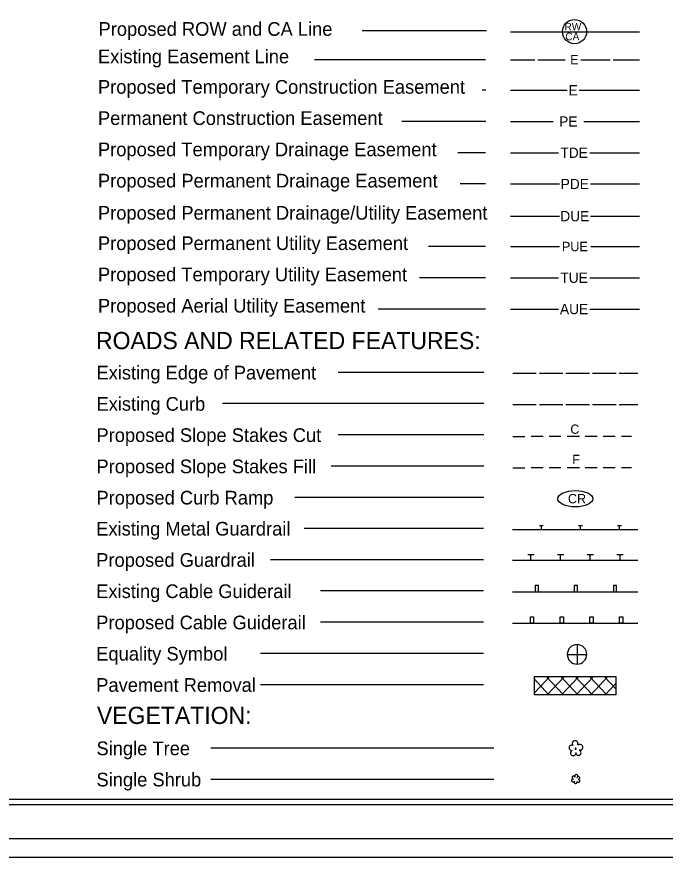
# Model space of a CAD drawing. Extents: x 811508 to 813252, y 647626 to 648754.
# Drawn here: x 811937 to 812366, y 647626 to 648182 of the extents above; entities that cross this region are included whole.
import ezdxf

# ---------------------------------------------------------------- set-up
doc = ezdxf.new("R2010")
doc.units = 0
for name, color, linetype in [('P_RDY_Easement_Permanent', 7, 'Continuous'), ('P_RDY_Easement_Permanent_Drainage_Utility', 7, 'Continuous'), ('P_RDY_WCC_CELL', 7, 'Continuous'), ('Sheet Cutting Line CELL', 7, 'Continuous'), ('Sheet Plot Border Inside CELL', 7, 'Continuous'), ('Sheet Plot Border Outside CELL', 7, 'Continuous'), ('Sheet_Plan', 7, 'Continuous'), ('Sheet_Symbology', 7, 'Continuous'), ('z - Construction', 7, 'Continuous')]:
    doc.layers.add(name, color=color, linetype=linetype)

msp = doc.modelspace()

# ---------------------------------------------------------------- linework, layer by layer
at = {"layer": 'P_RDY_Easement_Permanent'}
for p, q in [((812264.02, 648112.84), (812292.21, 648112.84)), ((812312.7, 648112.84), (812340.89, 648112.84)), ((812340.89, 648112.84), (812349.4, 648112.84))]:
    msp.add_line(p, q, dxfattribs=at)
at = {"layer": 'P_RDY_Easement_Permanent_Drainage_Utility'}
for p, q in [((812264.02, 648050.14), (812296.41, 648050.14)), ((812317.11, 648050.14), (812349.4, 648050.14))]:
    msp.add_line(p, q, dxfattribs=at)
at = {"layer": 'P_RDY_WCC_CELL'}
msp.add_ellipse((812306.97, 647863), major_axis=(11.61, 0), ratio=0.462467, dxfattribs=at)
at = {"layer": 'Sheet Cutting Line CELL'}
msp.add_line((811533.6, 647637.99), (813217.6, 647637.99), dxfattribs=at)
at = {"layer": 'Sheet Plot Border Inside CELL'}
msp.add_lwpolyline([(811546.6, 647660.44), (813213.1, 647660.44), (813213.1, 648715.54), (811546.6, 648715.54)], close=True, dxfattribs=at)
at = {"layer": 'Sheet Plot Border Outside CELL'}
msp.add_lwpolyline([(811533.6, 647637.99), (813217.6, 647637.99), (813217.6, 648737.99), (811533.6, 648737.99)], close=True, dxfattribs=at)
at = {"layer": 'Sheet_Plan'}
msp.add_line((811546.61, 647664.09), (813213.5, 647664.09), dxfattribs=at)
at = {"layer": 'Sheet_Symbology'}
for p, q in [((812248.08, 648172.94), (812165.95, 648172.94)), ((812264.03, 648172.14), (812349.41, 648172.14)), ((812247.43, 648153.67), (812134.36, 648153.67)), ((812264.02, 648153.67), (812280.07, 648153.67)), ((812282.14, 648153.67), (812300.26, 648153.67)), ((812310.61, 648153.67), (812330.01, 648153.67)), ((812332.08, 648153.67), (812349.4, 648153.67)), ((812247.83, 648133.54), (812245.22, 648133.54)), ((812264.02, 648133.54), (812266.72, 648133.54)), ((812266.72, 648133.54), (812301.65, 648133.54)), ((812309.42, 648133.54), (812344.35, 648133.54)), ((812344.35, 648133.54), (812349.4, 648133.54)), ((812247.83, 648112.84), (812192.14, 648112.84)), ((812247.43, 648092.14), (812229.32, 648092.14)), ((812264.02, 648092.14), (812267.49, 648092.14)), ((812267.49, 648092.14), (812295.95, 648092.14)), ((812316.65, 648092.14), (812345.11, 648092.14)), ((812345.11, 648092.14), (812349.4, 648092.14)), ((812247.43, 648071.44), (812230.86, 648071.44)), ((812264.02, 648071.44), (812267.95, 648071.44)), ((812267.95, 648071.44), (812296.41, 648071.44)), ((812317.11, 648071.44), (812345.57, 648071.44)), ((812345.57, 648071.44), (812349.4, 648071.44)), ((812247.43, 648030.03), (812209.74, 648030.03)), ((812264.02, 648030.03), (812267.99, 648030.03)), ((812267.99, 648030.03), (812296.45, 648030.03)), ((812317.15, 648030.03), (812345.61, 648030.03)), ((812345.61, 648030.03), (812349.4, 648030.03)), ((812247.43, 648009.33), (812203.82, 648009.33)), ((812264.02, 648009.33), (812267.49, 648009.33)), ((812267.49, 648009.33), (812295.95, 648009.33)), ((812316.65, 648009.33), (812345.11, 648009.33)), ((812345.11, 648009.33), (812349.4, 648009.33)), ((812247.43, 647988.63), (812176.58, 647988.63)), ((812264.02, 647988.63), (812267.49, 647988.63)), ((812267.49, 647988.63), (812295.95, 647988.63)), ((812316.65, 647988.63), (812345.11, 647988.63)), ((812345.11, 647988.63), (812349.4, 647988.63)), ((812246.43, 647946.69), (812149.93, 647946.69)), ((812265.61, 647946.1), (812281.14, 647946.1)), ((812283.21, 647946.1), (812298.73, 647946.1)), ((812300.8, 647946.1), (812316.32, 647946.1)), ((812318.39, 647946.1), (812333.92, 647946.1)), ((812335.99, 647946.1), (812348.41, 647946.1)), ((812246.43, 647925.99), (812073.44, 647925.99)), ((812265.61, 647925.4), (812281.14, 647925.4)), ((812283.21, 647925.4), (812298.73, 647925.4)), ((812300.8, 647925.4), (812316.32, 647925.4)), ((812318.39, 647925.4), (812333.92, 647925.4)), ((812335.99, 647925.4), (812348.41, 647925.4)), ((812246.43, 647905.29), (812149.99, 647905.29)), ((812265.61, 647904.21), (812273.48, 647904.21)), ((812285.59, 647904.21), (812277.77, 647904.21)), ((812297.49, 647904.21), (812289.62, 647904.21)), ((812309.65, 647904.21), (812301.58, 647904.21)), ((812321.5, 647904.21), (812313.48, 647904.21)), ((812333.45, 647904.21), (812325.33, 647904.21)), ((812344.11, 647904.21), (812337.49, 647904.21)), ((812246.43, 647884.59), (812145.28, 647884.59)), ((812265.61, 647883.51), (812273.48, 647883.51)), ((812285.59, 647883.51), (812277.77, 647883.51)), ((812297.49, 647883.51), (812289.62, 647883.51)), ((812309.65, 647883.51), (812301.58, 647883.51)), ((812321.5, 647883.51), (812313.48, 647883.51)), ((812333.45, 647883.51), (812325.33, 647883.51)), ((812344.11, 647883.51), (812337.49, 647883.51)), ((812246.43, 647863.89), (812121.28, 647863.89)), ((812283.19, 647845.31), (812285.77, 647845.31)), ((812284.48, 647842.72), (812284.48, 647845.31)), ((812309.06, 647845.31), (812311.65, 647845.31)), ((812310.35, 647842.72), (812310.35, 647845.31)), ((812334.93, 647845.31), (812337.52, 647845.31)), ((812336.23, 647842.72), (812336.23, 647845.31)), ((812246.27, 647843.32), (812127.42, 647843.32)), ((812265.45, 647842.72), (812348.25, 647842.72)), ((812246.27, 647822.62), (812105.27, 647822.62)), ((812348.25, 647822.02), (812265.45, 647822.02)), ((812275.51, 647826.11), (812279.65, 647826.11)), ((812277.58, 647822.02), (812277.58, 647826.11)), ((812295.18, 647826.11), (812299.32, 647826.11)), ((812297.25, 647822.02), (812297.25, 647826.11)), ((812314.84, 647826.11), (812318.98, 647826.11)), ((812316.91, 647822.02), (812316.91, 647826.11)), ((812334.51, 647826.11), (812338.65, 647826.11)), ((812336.58, 647822.02), (812336.58, 647826.11)), ((812246.27, 647801.92), (812138.32, 647801.92)), ((812265.45, 647801.32), (812348.25, 647801.32)), ((812246.27, 647781.22), (812138.32, 647781.22)), ((812265.45, 647780.63), (812348.25, 647780.63)), ((812308.12, 647766.38), (812308.12, 647759.91)), ((812246.27, 647760.52), (812098.66, 647760.52)), ((812301.65, 647759.91), (812308.12, 647759.91)), ((812308.12, 647759.91), (812308.12, 647753.44)), ((812308.12, 647759.91), (812314.58, 647759.91)), ((812279.89, 647745.29), (812333.81, 647745.29)), ((812279.89, 647733.18), (812279.89, 647745.29)), ((812279.89, 647744.67), (812280.46, 647745.29)), ((812279.89, 647734.37), (812290.08, 647745.29)), ((812299.09, 647733.18), (812287.7, 647745.29)), ((812288.32, 647733.18), (812299.71, 647745.29)), ((812308.66, 647733.18), (812297.33, 647745.29)), ((812297.89, 647733.18), (812309.33, 647745.29)), ((812318.28, 647733.18), (812306.9, 647745.29)), ((812307.52, 647733.18), (812318.9, 647745.29)), ((812327.91, 647733.18), (812316.47, 647745.29)), ((812317.15, 647733.18), (812328.48, 647745.29)), ((812333.81, 647737.07), (812326.1, 647745.29)), ((812333.81, 647745.29), (812333.81, 647733.18)), ((812246.27, 647739.82), (812098.66, 647739.82)), ((812289.46, 647733.18), (812279.89, 647743.43)), ((812326.72, 647733.18), (812333.81, 647740.74)), ((812333.81, 647733.18), (812279.89, 647733.18)), ((812253.08, 647697.86), (812065.62, 647697.86)), ((812253.08, 647677.16), (812065.62, 647677.16))]:
    msp.add_line(p, q, dxfattribs=at)
for points in [[(812280.43, 647801.32), (812282.5, 647801.32), (812282.5, 647805.46), (812280.43, 647805.46)], [(812306.3, 647801.32), (812308.37, 647801.32), (812308.37, 647805.46), (812306.3, 647805.46)], [(812332.18, 647801.32), (812334.25, 647801.32), (812334.25, 647805.46), (812332.18, 647805.46)], [(812277.31, 647784.76), (812279.38, 647784.76), (812279.38, 647780.63), (812277.31, 647780.63)], [(812296.98, 647784.76), (812299.05, 647784.76), (812299.05, 647780.63), (812296.98, 647780.63)], [(812316.64, 647784.76), (812318.71, 647784.76), (812318.71, 647780.63), (812316.64, 647780.63)], [(812336.31, 647784.76), (812338.38, 647784.76), (812338.38, 647780.63), (812336.31, 647780.63)]]:
    msp.add_lwpolyline(points, close=True, dxfattribs=at)
for points in [[(812308.49, 647700.02), (812308.65, 647700.39), (812308.73, 647700.75), (812308.69, 647701.16), (812308.61, 647701.53), (812308.41, 647701.89), (812308.2, 647702.18), (812307.88, 647702.47), (812307.55, 647702.63), (812307.14, 647702.75), (812306.78, 647702.75), (812306.37, 647702.71), (812306, 647702.59), (812305.68, 647702.38), (812305.39, 647702.1), (812305.19, 647701.77), (812305.02, 647701.41), (812304.98, 647701.04), (812304.98, 647700.63), (812305.06, 647700.26), (812305.23, 647699.9), (812305.47, 647699.57), (812305.15, 647699.73), (812304.78, 647699.82), (812304.41, 647699.78), (812304.05, 647699.69), (812303.72, 647699.53), (812303.39, 647699.29), (812303.19, 647699), (812302.99, 647698.67), (812302.91, 647698.35), (812302.86, 647697.94), (812302.91, 647697.57), (812303.07, 647697.25), (812303.27, 647696.92), (812303.52, 647696.68), (812303.84, 647696.47), (812304.17, 647696.31), (812304.54, 647696.27), (812304.9, 647696.27), (812304.58, 647696.11), (812304.29, 647695.86), (812304.09, 647695.58), (812303.92, 647695.21), (812303.84, 647694.85), (812303.8, 647694.48), (812303.88, 647694.11), (812304.05, 647693.79), (812304.25, 647693.46), (812304.49, 647693.21), (812304.82, 647693.01), (812305.19, 647692.89), (812305.55, 647692.85), (812305.92, 647692.89), (812306.29, 647692.97), (812306.61, 647693.17), (812306.9, 647693.42), (812307.1, 647693.7), (812307.27, 647694.03), (812307.35, 647694.4)], [(812307.22, 647694.85), (812307.27, 647694.44), (812307.39, 647694.07), (812307.59, 647693.75), (812307.88, 647693.46), (812308.2, 647693.25), (812308.57, 647693.13), (812308.98, 647693.09), (812309.34, 647693.13), (812309.71, 647693.25), (812310.04, 647693.46), (812310.32, 647693.7), (812310.57, 647694.03), (812310.69, 647694.4), (812310.77, 647694.76), (812310.73, 647695.17), (812310.65, 647695.54), (812310.44, 647695.9), (812310.2, 647696.19), (812309.87, 647696.39), (812309.51, 647696.56), (812309.91, 647696.52), (812310.32, 647696.52), (812310.69, 647696.64), (812311.05, 647696.8), (812311.38, 647697.05), (812311.63, 647697.37), (812311.83, 647697.74), (812311.91, 647698.1), (812311.95, 647698.51), (812311.87, 647698.92), (812311.75, 647699.29), (812311.5, 647699.61), (812311.22, 647699.9), (812310.89, 647700.1), (812310.48, 647700.26), (812310.12, 647700.3), (812309.71, 647700.3), (812309.3, 647700.18), (812308.98, 647699.98), (812308.65, 647699.73)], [(812307.35, 647697.74), (812307.18, 647697.74), (812307.02, 647697.7), (812306.94, 647697.57), (812306.9, 647697.41), (812306.94, 647697.25), (812307.06, 647697.13), (812307.22, 647697.13), (812307.39, 647697.17), (812307.51, 647697.29), (812307.55, 647697.45), (812307.47, 647697.62), (812307.35, 647697.74)], [(812306.74, 647678.67), (812306.61, 647678.91), (812306.37, 647679.12), (812306.12, 647679.28), (812305.84, 647679.32), (812305.55, 647679.28), (812305.27, 647679.2), (812305.02, 647679), (812304.86, 647678.75), (812304.78, 647678.46), (812304.78, 647678.18), (812304.86, 647677.89), (812305.02, 647677.65), (812305.27, 647677.45), (812305.55, 647677.32), (812305.84, 647677.32), (812305.55, 647677.36), (812305.27, 647677.36), (812305.02, 647677.28), (812304.78, 647677.12), (812304.62, 647676.92), (812304.54, 647676.67), (812304.49, 647676.39), (812304.54, 647676.1), (812304.66, 647675.86), (812304.86, 647675.65), (812305.1, 647675.53), (812305.35, 647675.45), (812305.64, 647675.49), (812305.88, 647675.57), (812306.12, 647675.73), (812306.29, 647675.94), (812306.16, 647675.65), (812306.12, 647675.37), (812306.21, 647675.08), (812306.33, 647674.84), (812306.53, 647674.59), (812306.78, 647674.47), (812307.06, 647674.39), (812307.35, 647674.43), (812307.63, 647674.51), (812307.88, 647674.67), (812308.04, 647674.92), (812308.16, 647675.2), (812308.16, 647675.49), (812308.12, 647675.77), (812308.24, 647675.57), (812308.49, 647675.37), (812308.73, 647675.29), (812309.02, 647675.25), (812309.3, 647675.29), (812309.55, 647675.41), (812309.75, 647675.61), (812309.87, 647675.86), (812309.91, 647676.14), (812309.91, 647676.43), (812309.79, 647676.67), (812309.63, 647676.88), (812309.42, 647677.04), (812309.14, 647677.16), (812308.85, 647677.16), (812309.14, 647677.16), (812309.42, 647677.24), (812309.63, 647677.4), (812309.83, 647677.65), (812309.91, 647677.89), (812309.91, 647678.18), (812309.87, 647678.46), (812309.71, 647678.71), (812309.51, 647678.87), (812309.22, 647679), (812308.94, 647679.04), (812308.69, 647678.95), (812308.41, 647678.83), (812308.24, 647678.63), (812308.12, 647678.38)], [(812308, 647678.38), (812308.24, 647678.5), (812308.45, 647678.75), (812308.57, 647679), (812308.61, 647679.28), (812308.61, 647679.56), (812308.49, 647679.85), (812308.32, 647680.05), (812308.12, 647680.26), (812307.84, 647680.34), (812307.55, 647680.38), (812307.27, 647680.34), (812307.02, 647680.22), (812306.78, 647680.01), (812306.65, 647679.77), (812306.57, 647679.48), (812306.57, 647679.2), (812306.61, 647678.91), (812306.78, 647678.67)]]:
    msp.add_lwpolyline(points, dxfattribs=at)
msp.add_circle((812306.45, 648172.3), 7.99, dxfattribs=at)
for start, end in [(89.9944, 179.9989), (359.9944, 89.9989), (179.9944, 269.9989), (269.9944, 359.9989)]:
    msp.add_arc((812308.12, 647759.91), 6.47, start, end, dxfattribs=at)
at = {"layer": 'z - Construction'}
msp.add_line((811508.14, 647625.63), (813251.99, 647625.63), dxfattribs=at)

# ---------------------------------------------------------------- texts
at = {"layer": 'P_RDY_Easement_Permanent_Drainage_Utility'}
msp.add_text('DUE', height=6.779, dxfattribs=at).set_placement((812297.03, 648046.73))
at = {"layer": 'P_RDY_WCC_CELL'}
msp.add_text('CR', height=6.21, dxfattribs=at).set_placement((812302.09, 647859.94))
at = {"layer": 'Sheet_Symbology'}
for s, height, p in [('Proposed ROW and CA Line', 9.056, (811991.39, 648169.55)), ('RW', 5.008, (812299.78, 648173.09)), ('CA', 5.008, (812300.35, 648166.58)), ('Existing Easement Line', 9.056, (811991.01, 648151.33)), ('E', 6.21, (812303.57, 648150.57)), ('Proposed Temporary Construction Easement', 9.056, (811991.01, 648131.2)), ('E', 6.78, (812302.54, 648130.12)), ('Permanent Construction Easement', 9.056, (811991.01, 648110.5)), ('PE', 6.779, (812296.29, 648109.42)), ('Proposed Temporary Drainage Easement', 9.056, (811991.01, 648089.8)), ('TDE', 6.779, (812297.1, 648088.72)), ('Proposed Permanent Drainage Easement', 9.056, (811991.01, 648069.1)), ('PDE', 6.779, (812297.29, 648068.03)), ('Proposed Permanent Drainage/Utility Easement', 9.056, (811991.01, 648047.8)), ('Proposed Permanent Utility Easement', 9.056, (811991.01, 648027.69)), ('PUE', 6.21, (812298.12, 648026.93)), ('Proposed Temporary Utility Easement', 9.056, (811991.01, 648006.99)), ('TUE', 6.779, (812297.1, 648005.92)), ('Proposed Aerial Utility Easement', 9.056, (811991.01, 647986.29)), ('AUE', 6.779, (812296.83, 647985.22)), ('ROADS AND RELATED FEATURES:', 11.3847, (811989.71, 647962.05)), ('Existing Edge of Pavement', 9.056, (811990.02, 647941.98)), ('Existing Curb', 9.056, (811990.02, 647921.28)), ('C', 6.13, (812303.7, 647906)), ('Proposed Slope Stakes Cut', 9.056, (811990.02, 647900.58)), ('Proposed Slope Stakes Fill', 9.056, (811990.02, 647879.88)), ('F', 6.13, (812304.94, 647885.95)), ('Proposed Curb Ramp', 9.056, (811990.02, 647859.18)), ('Existing Metal Guardrail', 9.056, (811989.86, 647838.61)), ('Proposed Guardrail', 9.056, (811989.87, 647817.92)), ('Existing Cable Guiderail', 9.056, (811989.87, 647797.22)), ('Proposed Cable Guiderail', 9.056, (811989.87, 647776.52)), ('Equality Symbol', 9.056, (811989.87, 647755.82)), ('Pavement Removal', 9.056, (811989.87, 647735.13)), ('VEGETATION:', 11.3847, (811990.32, 647713.85)), ('Single Tree', 9.056, (811990.03, 647693.18)), ('Single Shrub', 9.056, (811990.03, 647672.48))]:
    msp.add_text(s, height=height, dxfattribs=at).set_placement(p)

doc.saveas('drawing.dxf')
